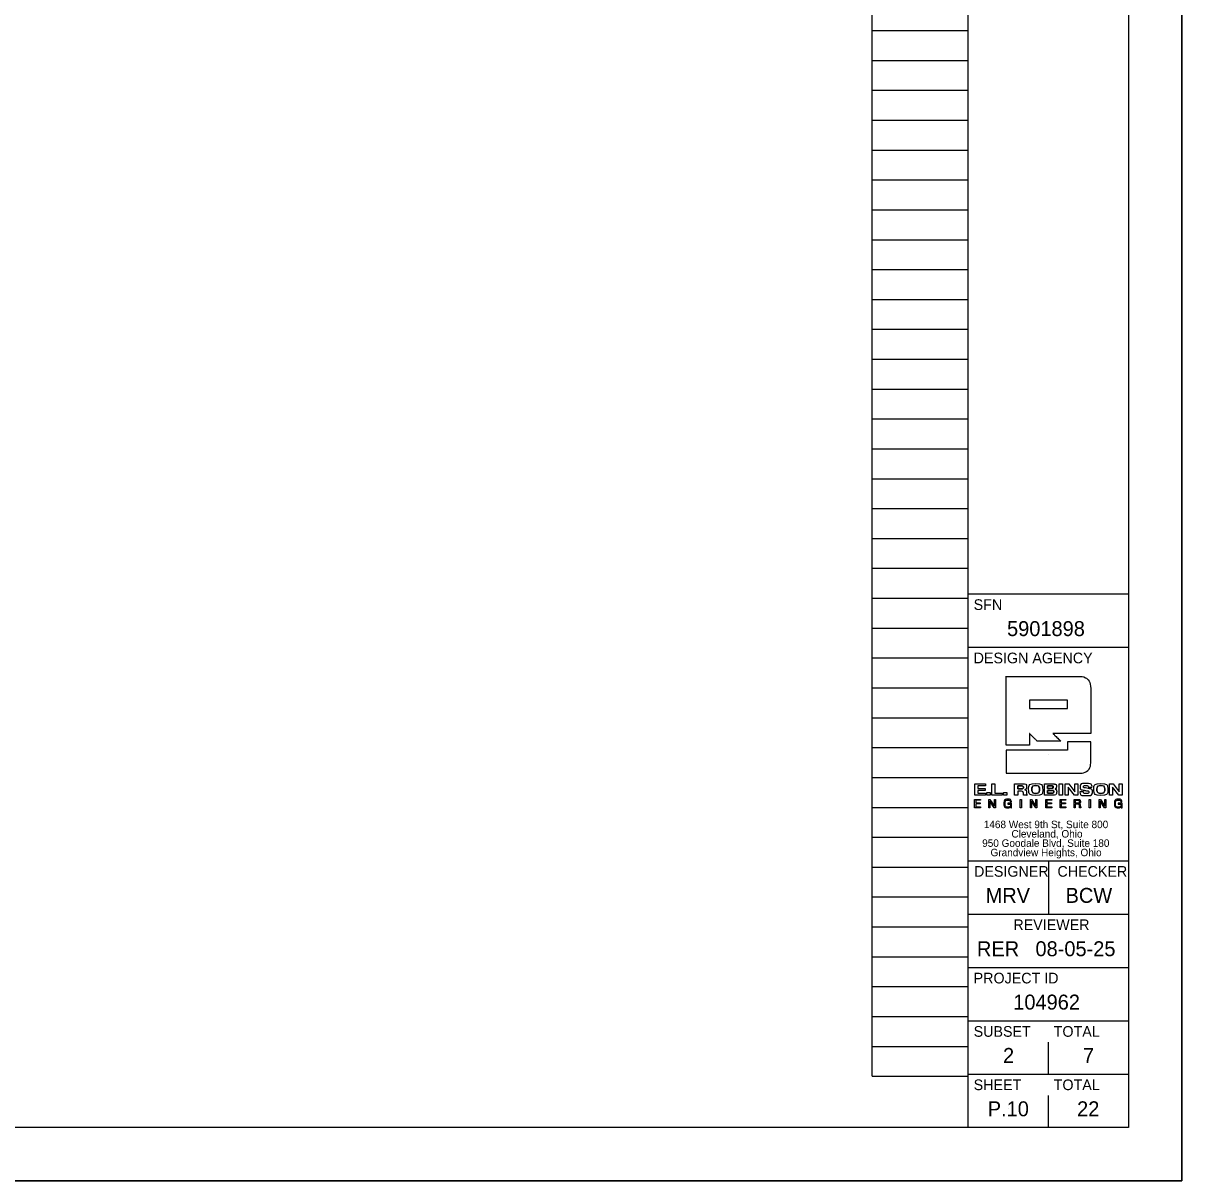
# Model space of a CAD drawing. Extents: x 0 to 64.5, y 0 to 22.
# Drawn here: x 23.15 to 34, y 0 to 10.85 of the extents above; entities that cross this region are included whole.
import ezdxf

# ---------------------------------------------------------------- set-up
doc = ezdxf.new("R2010")
doc.units = 0
for name, color, linetype in [('SC_Scratch1', 7, 'Continuous'), ('SH_Border', 7, 'Continuous'), ('SH_Cut_Line', 7, 'Continuous'), ('SH_Data', 7, 'Continuous')]:
    doc.layers.add(name, color=color, linetype=linetype)

msp = doc.modelspace()

# ---------------------------------------------------------------- linework, layer by layer
at = {"layer": 'SC_Scratch1'}
for p, q in [((31.1, 0.98), (31.1, 21.14)), ((32, 0.98), (32, 21.14)), ((31.1, 10.78), (32, 10.78)), ((31.1, 10.5), (32, 10.5)), ((31.1, 10.22), (32, 10.22)), ((31.1, 9.94), (32, 9.94)), ((31.1, 9.66), (32, 9.66)), ((31.1, 9.38), (32, 9.38)), ((31.1, 9.1), (32, 9.1)), ((31.1, 8.82), (32, 8.82)), ((31.1, 8.54), (32, 8.54)), ((31.1, 8.26), (32, 8.26)), ((31.1, 7.98), (32, 7.98)), ((31.1, 7.7), (32, 7.7)), ((31.1, 7.42), (32, 7.42)), ((31.1, 7.14), (32, 7.14)), ((31.1, 6.86), (32, 6.86)), ((31.1, 6.58), (32, 6.58)), ((31.1, 6.3), (32, 6.3)), ((31.1, 6.02), (32, 6.02)), ((31.1, 5.74), (32, 5.74)), ((31.1, 5.46), (32, 5.46)), ((31.1, 5.18), (32, 5.18)), ((31.1, 4.9), (32, 4.9)), ((31.1, 4.62), (32, 4.62)), ((31.1, 4.34), (32, 4.34)), ((31.1, 4.06), (32, 4.06)), ((31.1, 3.78), (32, 3.78)), ((31.1, 3.5), (32, 3.5)), ((31.1, 3.22), (32, 3.22)), ((31.1, 2.94), (32, 2.94)), ((31.1, 2.66), (32, 2.66)), ((31.1, 2.38), (32, 2.38)), ((31.1, 2.1), (32, 2.1)), ((31.1, 1.82), (32, 1.82)), ((31.1, 1.54), (32, 1.54)), ((31.1, 1.26), (32, 1.26)), ((31.1, 0.98), (32, 0.98))]:
    msp.add_line(p, q, dxfattribs=at)
msp.add_lwpolyline([(0, 22), (34, 22), (34, 0), (0, 0)], close=True, dxfattribs=at)
at = {"layer": 'SH_Border'}
for p, q in [((32, 0.5), (32, 21.5)), ((32, 5.5), (33.5, 5.5)), ((32, 5), (33.5, 5)), ((32, 3), (33.5, 3)), ((32.75, 3), (32.75, 2.5)), ((32, 2.5), (33.5, 2.5)), ((32, 2), (33.5, 2)), ((32, 1.5), (33.5, 1.5)), ((32, 1), (33.5, 1))]:
    msp.add_line(p, q, dxfattribs=at)
msp.add_lwpolyline([(1.5, 21.5), (33.5, 21.5), (33.5, 0.5), (1.5, 0.5)], close=True, dxfattribs=at)
at = {"layer": 'SH_Cut_Line'}
msp.add_lwpolyline([(0, 0), (34, 0), (34, 22), (0, 22)], close=True, dxfattribs=at)
at = {"layer": 'SH_Data'}
for p, q in [((32.929, 4.503), (32.574, 4.503)), ((32.574, 4.503), (32.574, 4.425)), ((32.929, 4.425), (32.929, 4.503)), ((32.574, 4.425), (32.929, 4.425)), ((32.75, 4), (32.75, 4)), ((32.463, 3.701), (32.463, 3.673)), ((32.743, 3.702), (32.743, 3.678)), ((32.743, 3.659), (32.743, 3.633)), ((33.001, 3.566), (33.001, 3.539)), ((33.001, 3.539), (33.023, 3.539)), ((32.75, 1), (32.75, 1.3)), ((32.75, 0.5), (32.75, 0.8)), ((32.375, 0.675), (32.375, 0.675))]:
    msp.add_line(p, q, dxfattribs=at)
for points in [[(32.06, 3.721), (32.161, 3.721), (32.161, 3.701), (32.089, 3.701), (32.089, 3.678), (32.158, 3.678), (32.158, 3.658), (32.089, 3.658), (32.089, 3.633), (32.162, 3.633), (32.162, 3.613), (32.06, 3.613), (32.06, 3.721)], [(32.22, 3.721), (32.249, 3.721), (32.249, 3.634), (32.316, 3.634), (32.316, 3.613), (32.22, 3.613), (32.22, 3.721)], [(32.851, 3.721), (32.881, 3.721), (32.881, 3.613), (32.851, 3.613), (32.851, 3.721)], [(32.999, 3.721), (33.027, 3.721), (33.027, 3.613), (32.995, 3.613), (32.936, 3.689), (32.936, 3.689), (32.936, 3.613), (32.907, 3.613), (32.907, 3.721), (32.941, 3.721), (32.999, 3.646), (32.999, 3.646), (32.999, 3.721)], [(33.413, 3.721), (33.442, 3.721), (33.442, 3.613), (33.41, 3.613), (33.35, 3.689), (33.35, 3.689), (33.35, 3.613), (33.321, 3.613), (33.321, 3.721), (33.356, 3.721), (33.413, 3.646), (33.413, 3.646), (33.413, 3.721)], [(32.175, 3.639), (32.205, 3.639), (32.205, 3.613), (32.175, 3.613), (32.175, 3.639)], [(32.331, 3.639), (32.361, 3.639), (32.361, 3.613), (32.331, 3.613), (32.331, 3.639)], [(32.059, 3.575), (32.114, 3.575), (32.114, 3.566), (32.07, 3.566), (32.07, 3.541), (32.111, 3.541), (32.111, 3.532), (32.07, 3.532), (32.07, 3.505), (32.114, 3.505), (32.114, 3.496), (32.059, 3.496), (32.059, 3.575)], [(32.191, 3.575), (32.203, 3.575), (32.244, 3.511), (32.244, 3.511), (32.244, 3.575), (32.254, 3.575), (32.254, 3.496), (32.243, 3.496), (32.202, 3.559), (32.201, 3.559), (32.201, 3.496), (32.191, 3.496), (32.191, 3.575)], [(32.487, 3.575), (32.498, 3.575), (32.498, 3.496), (32.487, 3.496), (32.487, 3.575)], [(32.581, 3.575), (32.592, 3.575), (32.633, 3.511), (32.633, 3.511), (32.633, 3.575), (32.643, 3.575), (32.643, 3.496), (32.632, 3.496), (32.591, 3.559), (32.591, 3.559), (32.591, 3.496), (32.581, 3.496), (32.581, 3.575)], [(32.726, 3.575), (32.781, 3.575), (32.781, 3.566), (32.737, 3.566), (32.737, 3.541), (32.778, 3.541), (32.778, 3.532), (32.737, 3.532), (32.737, 3.505), (32.781, 3.505), (32.781, 3.496), (32.726, 3.496), (32.726, 3.575)], [(32.859, 3.575), (32.913, 3.575), (32.913, 3.566), (32.869, 3.566), (32.869, 3.541), (32.91, 3.541), (32.91, 3.532), (32.869, 3.532), (32.869, 3.505), (32.913, 3.505), (32.913, 3.496), (32.859, 3.496), (32.859, 3.575)], [(33.133, 3.575), (33.143, 3.575), (33.143, 3.496), (33.133, 3.496), (33.133, 3.575)], [(33.226, 3.575), (33.237, 3.575), (33.279, 3.511), (33.279, 3.511), (33.279, 3.575), (33.289, 3.575), (33.289, 3.496), (33.277, 3.496), (33.236, 3.559), (33.236, 3.559), (33.236, 3.496), (33.226, 3.496), (33.226, 3.575)]]:
    msp.add_lwpolyline(points, dxfattribs=at)
for points, degree in [([(32.356, 4.083), (32.356, 4.086), (32.356, 4.724), (32.356, 4.727)], 2), ([(32.356, 4.727), (32.36, 4.727), (33.03, 4.727), (33.034, 4.727), (33.096, 4.727), (33.147, 4.677), (33.147, 4.614)], 3), ([(33.147, 4.614), (33.147, 4.612), (33.147, 4.194), (33.147, 4.192)], 2), ([(32.645, 4.121), (32.645, 4.121), (32.574, 4.191), (32.574, 4.192)], 2), ([(32.574, 4.192), (32.574, 4.191), (32.574, 4.083), (32.574, 4.083)], 2), ([(33.147, 4.192), (33.145, 4.192), (32.795, 4.192), (32.793, 4.192)], 2), ([(32.793, 4.192), (32.793, 4.191), (32.866, 4.121), (32.866, 4.121)], 2), ([(32.929, 4.115), (32.929, 4.115), (33.147, 4.115), (33.147, 4.115), (33.147, 4.115), (33.147, 3.933), (33.147, 3.933), (33.147, 3.87), (33.096, 3.82), (33.034, 3.82), (33.034, 3.82), (32.356, 3.82), (32.356, 3.82), (32.356, 3.82), (32.356, 4.037), (32.356, 4.037), (32.356, 4.037), (32.929, 4.037), (32.929, 4.037), (32.929, 4.037), (32.929, 4.115), (32.929, 4.115)], 3), ([(32.574, 4.083), (32.573, 4.083), (32.357, 4.083), (32.356, 4.083)], 2), ([(32.866, 4.121), (32.865, 4.121), (32.646, 4.121), (32.645, 4.121)], 2), ([(32.433, 3.613), (32.433, 3.613), (32.433, 3.721), (32.433, 3.721)], 2), ([(32.433, 3.721), (32.433, 3.721), (32.512, 3.721), (32.512, 3.721), (32.542, 3.721), (32.545, 3.703), (32.546, 3.692)], 3), ([(32.463, 3.673), (32.463, 3.673), (32.502, 3.673), (32.502, 3.673), (32.508, 3.673), (32.516, 3.677), (32.516, 3.687), (32.516, 3.698), (32.507, 3.701), (32.5, 3.701), (32.5, 3.701), (32.463, 3.701), (32.463, 3.701), (32.463, 3.701), (32.463, 3.673), (32.463, 3.673)], 3), ([(32.463, 3.673), (32.476, 3.673), (32.489, 3.673), (32.508, 3.673), (32.516, 3.677), (32.516, 3.698), (32.507, 3.701), (32.488, 3.701), (32.475, 3.701), (32.463, 3.701)], 3), ([(32.546, 3.692), (32.544, 3.679), (32.542, 3.67), (32.53, 3.666)], 2), ([(32.631, 3.61), (32.573, 3.61), (32.567, 3.645), (32.565, 3.667), (32.564, 3.69), (32.573, 3.724), (32.631, 3.724)], 3), ([(32.631, 3.63), (32.658, 3.63), (32.667, 3.65), (32.667, 3.667), (32.667, 3.684), (32.658, 3.704), (32.631, 3.704), (32.604, 3.704), (32.595, 3.684), (32.595, 3.667), (32.595, 3.65), (32.604, 3.63), (32.631, 3.63)], 3), ([(32.631, 3.704), (32.604, 3.704), (32.595, 3.684), (32.595, 3.667), (32.595, 3.65), (32.604, 3.63), (32.631, 3.63)], 3), ([(32.631, 3.724), (32.69, 3.724), (32.695, 3.689), (32.697, 3.667), (32.699, 3.644), (32.69, 3.61), (32.631, 3.61)], 3), ([(32.631, 3.63), (32.658, 3.63), (32.667, 3.65), (32.667, 3.667), (32.667, 3.684), (32.658, 3.704), (32.631, 3.704)], 3), ([(32.714, 3.613), (32.714, 3.613), (32.714, 3.721), (32.714, 3.721)], 2), ([(32.714, 3.721), (32.714, 3.721), (32.795, 3.721), (32.795, 3.721)], 2), ([(32.743, 3.678), (32.743, 3.678), (32.784, 3.678), (32.784, 3.678), (32.791, 3.678), (32.796, 3.682), (32.796, 3.69), (32.796, 3.697), (32.793, 3.702), (32.78, 3.702), (32.78, 3.702), (32.743, 3.702), (32.743, 3.702), (32.743, 3.702), (32.743, 3.678), (32.743, 3.678)], 3), ([(32.743, 3.678), (32.757, 3.678), (32.771, 3.678), (32.791, 3.681), (32.791, 3.683), (32.792, 3.697), (32.793, 3.702), (32.768, 3.702), (32.756, 3.702), (32.743, 3.702)], 3), ([(32.795, 3.721), (32.81, 3.718), (32.826, 3.714), (32.826, 3.694)], 2), ([(32.826, 3.694), (32.824, 3.686), (32.822, 3.675), (32.812, 3.672)], 2), ([(33.126, 3.69), (33.124, 3.704), (33.111, 3.706), (33.099, 3.706), (33.087, 3.706), (33.079, 3.7), (33.079, 3.693), (33.079, 3.687), (33.084, 3.684), (33.091, 3.683), (33.091, 3.683), (33.128, 3.677), (33.128, 3.677), (33.148, 3.673), (33.163, 3.666), (33.163, 3.646), (33.163, 3.626), (33.149, 3.61), (33.107, 3.61), (33.08, 3.61), (33.046, 3.613), (33.045, 3.647), (33.045, 3.647), (33.079, 3.647), (33.079, 3.647), (33.079, 3.632), (33.094, 3.629), (33.107, 3.629), (33.121, 3.629), (33.13, 3.634), (33.13, 3.643), (33.13, 3.651), (33.123, 3.654), (33.112, 3.655), (33.112, 3.655), (33.085, 3.66), (33.085, 3.66), (33.066, 3.662), (33.047, 3.668), (33.047, 3.69), (33.047, 3.715), (33.067, 3.724), (33.101, 3.724), (33.124, 3.724), (33.157, 3.721), (33.159, 3.69), (33.159, 3.69), (33.126, 3.69), (33.126, 3.69)], 3), ([(33.242, 3.61), (33.183, 3.61), (33.178, 3.645), (33.176, 3.667), (33.174, 3.69), (33.183, 3.724), (33.242, 3.724)], 3), ([(33.242, 3.63), (33.269, 3.63), (33.278, 3.65), (33.278, 3.667), (33.278, 3.684), (33.269, 3.704), (33.242, 3.704), (33.215, 3.704), (33.205, 3.684), (33.205, 3.667), (33.205, 3.65), (33.215, 3.63), (33.242, 3.63)], 3), ([(33.242, 3.704), (33.215, 3.704), (33.205, 3.684), (33.205, 3.667), (33.205, 3.65), (33.215, 3.63), (33.242, 3.63)], 3), ([(33.242, 3.724), (33.3, 3.724), (33.306, 3.689), (33.308, 3.667), (33.309, 3.644), (33.3, 3.61), (33.242, 3.61)], 3), ([(33.242, 3.63), (33.269, 3.63), (33.278, 3.65), (33.278, 3.667), (33.278, 3.684), (33.269, 3.704), (33.242, 3.704)], 3), ([(32.463, 3.613), (32.462, 3.613), (32.433, 3.613), (32.433, 3.613)], 2), ([(32.499, 3.653), (32.499, 3.653), (32.463, 3.653), (32.463, 3.653)], 2), ([(32.463, 3.653), (32.463, 3.652), (32.463, 3.613), (32.463, 3.613)], 2), ([(32.518, 3.613), (32.516, 3.618), (32.516, 3.622), (32.516, 3.634), (32.515, 3.649), (32.508, 3.65), (32.499, 3.653)], 3), ([(32.55, 3.613), (32.55, 3.613), (32.518, 3.613), (32.518, 3.613)], 2), ([(32.53, 3.666), (32.53, 3.666), (32.53, 3.665), (32.53, 3.665)], 2), ([(32.53, 3.665), (32.543, 3.663), (32.544, 3.647), (32.544, 3.636)], 2), ([(32.544, 3.636), (32.544, 3.631), (32.548, 3.619), (32.55, 3.613)], 2), ([(32.829, 3.645), (32.827, 3.632), (32.824, 3.613), (32.791, 3.613), (32.791, 3.613), (32.714, 3.613), (32.714, 3.613)], 3), ([(32.743, 3.633), (32.743, 3.633), (32.787, 3.633), (32.787, 3.633), (32.796, 3.633), (32.8, 3.639), (32.8, 3.646), (32.8, 3.655), (32.794, 3.659), (32.784, 3.659), (32.784, 3.659), (32.743, 3.659), (32.743, 3.659), (32.743, 3.659), (32.743, 3.633), (32.743, 3.633)], 3), ([(32.743, 3.633), (32.758, 3.633), (32.772, 3.633), (32.796, 3.633), (32.8, 3.639), (32.8, 3.655), (32.794, 3.659), (32.77, 3.659), (32.757, 3.659), (32.743, 3.659)], 3), ([(32.812, 3.672), (32.812, 3.672), (32.812, 3.672), (32.812, 3.672)], 2), ([(32.812, 3.672), (32.824, 3.67), (32.827, 3.656), (32.829, 3.645)], 2), ([(32.396, 3.506), (32.39, 3.498), (32.38, 3.494), (32.37, 3.494), (32.347, 3.494), (32.333, 3.514), (32.333, 3.534), (32.333, 3.557), (32.346, 3.577), (32.37, 3.577), (32.388, 3.577), (32.401, 3.569), (32.404, 3.551), (32.404, 3.551), (32.394, 3.551), (32.394, 3.551), (32.392, 3.562), (32.382, 3.568), (32.37, 3.568), (32.351, 3.568), (32.344, 3.551), (32.344, 3.534), (32.344, 3.518), (32.353, 3.503), (32.37, 3.503), (32.387, 3.503), (32.396, 3.515), (32.396, 3.529), (32.396, 3.529), (32.371, 3.529), (32.371, 3.529), (32.371, 3.529), (32.371, 3.538), (32.371, 3.538), (32.371, 3.538), (32.405, 3.538), (32.405, 3.538), (32.405, 3.538), (32.405, 3.496), (32.405, 3.496), (32.405, 3.496), (32.398, 3.496), (32.398, 3.496), (32.398, 3.496), (32.396, 3.506), (32.396, 3.506)], 3), ([(32.991, 3.575), (32.991, 3.575), (33.027, 3.575), (33.028, 3.575), (33.042, 3.575), (33.051, 3.567), (33.051, 3.554)], 3), ([(32.991, 3.496), (32.991, 3.497), (32.991, 3.574), (32.991, 3.575)], 2), ([(33.001, 3.496), (33.001, 3.496), (32.991, 3.496), (32.991, 3.496)], 2), ([(33.023, 3.539), (33.033, 3.539), (33.041, 3.541), (33.041, 3.552), (33.041, 3.56), (33.037, 3.566), (33.027, 3.566), (33.027, 3.566), (33.001, 3.566), (33.001, 3.566), (33.001, 3.566), (33.001, 3.539), (33.001, 3.539), (33.001, 3.539), (33.023, 3.539), (33.023, 3.539)], 3), ([(33.023, 3.539), (33.033, 3.539), (33.041, 3.541), (33.041, 3.56), (33.037, 3.566), (33.018, 3.566), (33.01, 3.566), (33.001, 3.566)], 3), ([(33.04, 3.516), (33.038, 3.523), (33.037, 3.53), (33.027, 3.53), (33.027, 3.53), (33.001, 3.53), (33.001, 3.53)], 3), ([(33.001, 3.53), (33.001, 3.53), (33.001, 3.496), (33.001, 3.496)], 2), ([(33.051, 3.554), (33.049, 3.545), (33.047, 3.537), (33.038, 3.534)], 2), ([(33.038, 3.534), (33.038, 3.534), (33.038, 3.534), (33.038, 3.534)], 2), ([(33.038, 3.534), (33.044, 3.529), (33.047, 3.525), (33.048, 3.518)], 2), ([(33.043, 3.496), (33.042, 3.5), (33.041, 3.508), (33.04, 3.516)], 2), ([(33.054, 3.496), (33.054, 3.496), (33.043, 3.496), (33.043, 3.496)], 2), ([(33.048, 3.518), (33.049, 3.51), (33.052, 3.502), (33.054, 3.496)], 2), ([(33.43, 3.506), (33.424, 3.498), (33.414, 3.494), (33.405, 3.494), (33.382, 3.494), (33.368, 3.514), (33.368, 3.534), (33.368, 3.557), (33.38, 3.577), (33.405, 3.577), (33.422, 3.577), (33.436, 3.569), (33.439, 3.551), (33.439, 3.551), (33.429, 3.551), (33.429, 3.551), (33.426, 3.562), (33.417, 3.568), (33.405, 3.568), (33.386, 3.568), (33.378, 3.551), (33.378, 3.534), (33.378, 3.518), (33.388, 3.503), (33.405, 3.503), (33.421, 3.503), (33.431, 3.515), (33.43, 3.529), (33.43, 3.529), (33.405, 3.529), (33.405, 3.529), (33.405, 3.529), (33.405, 3.538), (33.405, 3.538), (33.405, 3.538), (33.44, 3.538), (33.44, 3.538), (33.44, 3.538), (33.44, 3.496), (33.44, 3.496), (33.44, 3.496), (33.433, 3.496), (33.433, 3.496), (33.433, 3.496), (33.43, 3.506), (33.43, 3.506)], 3)]:
    msp.add_open_spline(points, degree=degree, dxfattribs=at)

# ---------------------------------------------------------------- texts
for s, height, p in [('SFN', 0.1, (32.05, 5.35)), ('5901898', 0.14, (32.363, 5.105)), ('DESIGN AGENCY', 0.1, (32.05, 4.85)), ('1468 West 9th St, Suite 800', 0.07, (32.145, 3.305)), ('Cleveland, Ohio', 0.07, (32.404, 3.217)), ('950 Goodale Blvd, Suite 180', 0.07, (32.13, 3.13)), ('Grandview Heights, Ohio', 0.07, (32.208, 3.042)), ('DESIGNER', 0.1, (32.054, 2.85)), ('CHECKER', 0.1, (32.835, 2.85)), ('MRV', 0.14, (32.162, 2.605)), ('BCW', 0.14, (32.911, 2.605)), ('REVIEWER', 0.1, (32.422, 2.35)), ('RER', 0.14, (32.081, 2.105)), ('08-05-25', 0.14, (32.629, 2.105)), ('PROJECT ID', 0.1, (32.05, 1.85)), ('104962', 0.14, (32.421, 1.605)), ('SUBSET', 0.1, (32.05, 1.35)), ('TOTAL', 0.1, (32.8, 1.35)), ('2', 0.14, (32.325, 1.105)), ('7', 0.14, (33.074, 1.105)), ('SHEET', 0.1, (32.05, 0.85)), ('TOTAL', 0.1, (32.8, 0.85)), ('P.10', 0.14, (32.182, 0.605)), ('22', 0.14, (33.019, 0.605))]:
    msp.add_text(s, height=height, dxfattribs=at).set_placement(p)

doc.saveas('drawing.dxf')
